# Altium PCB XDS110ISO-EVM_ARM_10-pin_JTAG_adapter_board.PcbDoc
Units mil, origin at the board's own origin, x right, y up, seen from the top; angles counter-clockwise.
Board outline 1100 x 500 mil, 2 copper layers (Top Signal, Bottom Signal), stack 58.8 mil thick; 2 components, 6 nets, 25 pads, 15 vias.
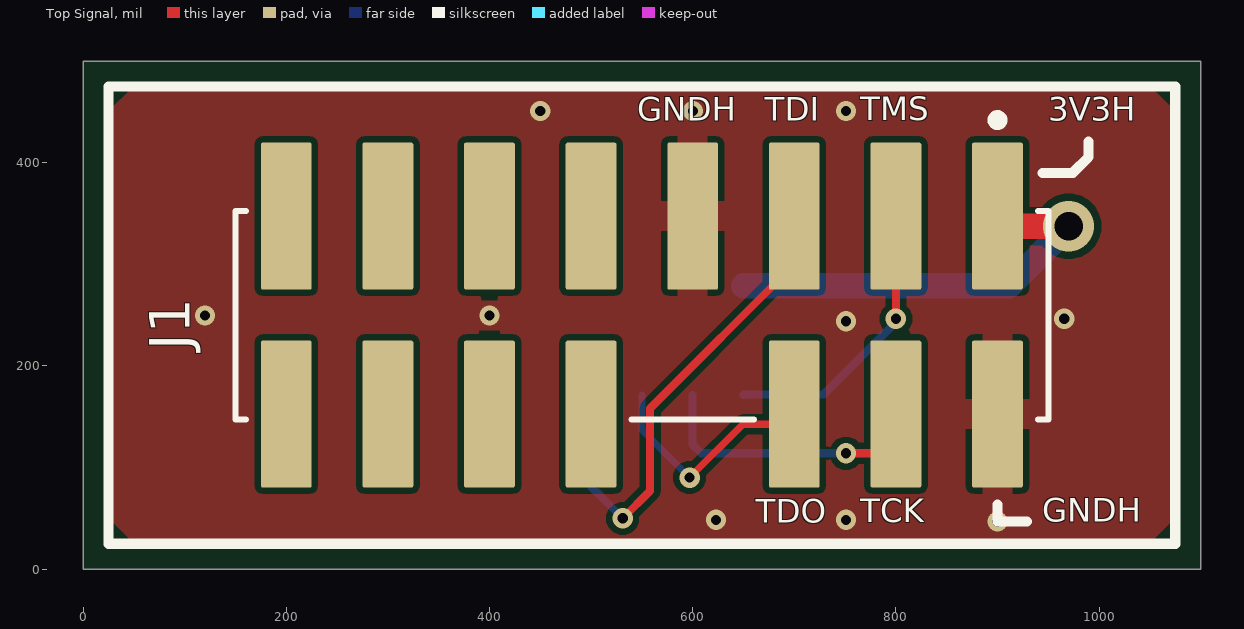
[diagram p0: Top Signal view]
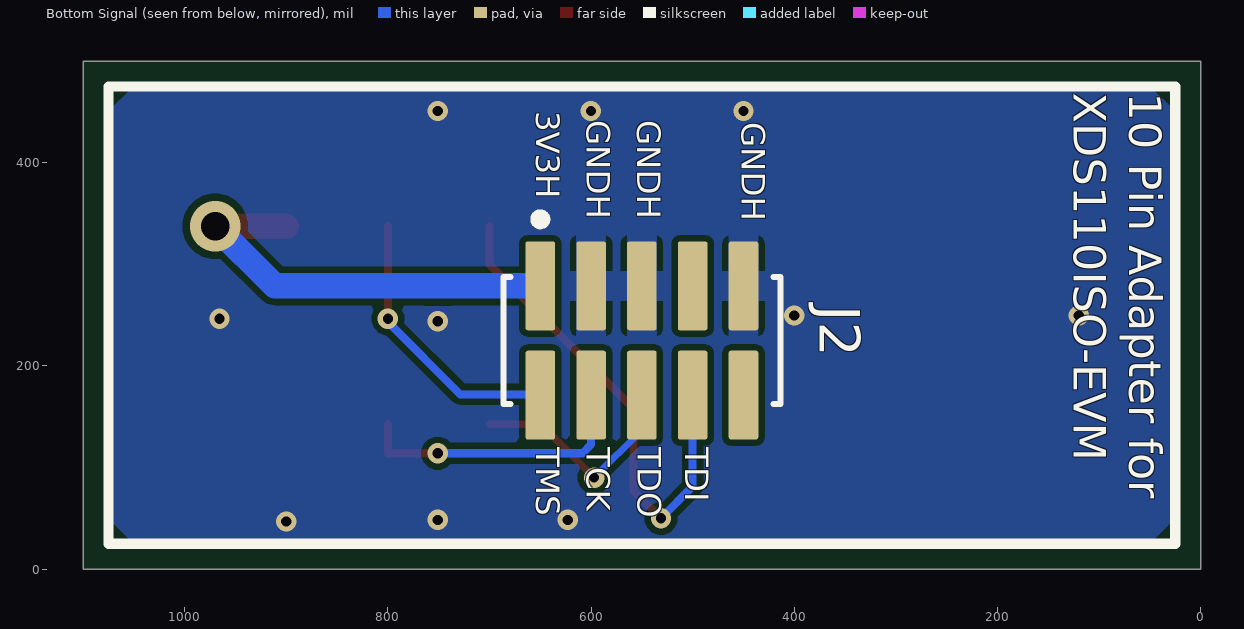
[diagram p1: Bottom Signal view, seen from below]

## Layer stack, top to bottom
Top Solder: solder mask 0.4, Solder Resist, Dk 3.5
Top Signal: signal copper 1.4
Dielectric 1: prepreg 8, FR-4, Dk 4.2
Dielectric 2: core 40, FR-4, Dk 4.2
Dielectric 3: prepreg 8, FR-4, Dk 4.2
Bottom Signal: signal copper 1.4
Bottom Solder: solder mask 0.4, Solder Resist, Dk 3.5

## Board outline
0,0 0,500 1100,500 1100,0

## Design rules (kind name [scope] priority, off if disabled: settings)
AcuteAngle [All] p1: minimum=4.50000000000000E+0001 checktracksonly=TRUE
AssemblyTestPointUsage [All] p1: valid=2
BoardOutlineClearance BoardOutlineClearance_MountingHoles [OnCopper and InComponentClass('Mounting Holes')] p1: gap=40 ignorepadtopadclearanceinfootprint=FALSE
BoardOutlineClearance BoardOutlineClearance_Poly [OnCopper and IsPoly] p2: gap=25 ignorepadtopadclearanceinfootprint=FALSE
BoardOutlineClearance BoardOutlineClearance_USB101 [InComponent('USB101')] p3: gap=0 ignorepadtopadclearanceinfootprint=FALSE
BoardOutlineClearance [OnCopper and Not InComponentClass('Logo') and not InComponentClass('FiducialMark') and not InRegion(1000,500,4000,800) and not InPoly] p4: gap=10 ignorepadtopadclearanceinfootprint=FALSE
Clearance Clearance_NPTH [HoleDiameter = 39] p1: gap=15 ignorepadtopadclearanceinfootprint=FALSE
Clearance Clearance_PTH [HoleDiameter > 10] p2: gap=7 ignorepadtopadclearanceinfootprint=FALSE
Clearance Clearance_FiducialMark [InComponentClass('FiducialMark') vs InComponentClass('FiducialMark')] p3: gap=0 ignorepadtopadclearanceinfootprint=FALSE
Clearance Clearance_Boardedge [All vs IsKeepOut] p4: gap=11.8 ignorepadtopadclearanceinfootprint=FALSE
Clearance [All] p5: gap=6 ignorepadtopadclearanceinfootprint=FALSE
ComponentClearance "ComponentClearance_overlay to overlay" [OnBottomSilkscreen vs OnTopSilkscreen] p1: gap=0 collisioncheckmode=3 verticalgap=0 showdistances=FALSE
ComponentClearance ComponentClearance_MountingHoles_FiducialMarks [InComponentClass('Mounting Holes') vs InComponentClass('FiducialMark')] p2: gap=50 collisioncheckmode=3 verticalgap=10 showdistances=FALSE
ComponentClearance ComponentClearance_Shunt [InComponentClass('Header') vs InComponentClass('Shunt')] p3: gap=0 collisioncheckmode=3 verticalgap=0 showdistances=FALSE
ComponentClearance ComponentClearance_Logo [InComponentClass('Logo')] p4: gap=0 collisioncheckmode=3 verticalgap=0 showdistances=FALSE
ComponentClearance ComponentClearance_Logo_1 [InComponentClass('Logo') vs InComponentClass('Logo')] p5: gap=0 collisioncheckmode=3 verticalgap=0 showdistances=FALSE
ComponentClearance ComponentClearance_ScrewToNut [(HasFootprint('NY PMS 440 0025 PH')) vs (HasFootprint('Keystone_1902C'))] p6: gap=3.94 collisioncheckmode=3 verticalgap=3.94 showdistances=FALSE
ComponentClearance ComponentClearance_MountingHoles [InComponentClass('Mounting Holes')] p7 off: gap=250 collisioncheckmode=3 verticalgap=100000 showdistances=FALSE
ComponentClearance ComponentClearance_SmallPassives [HasFootprint('0201*') or HasFootprint('0402*') or HasFootprint('0508') or HasFootprint('0603*') or HasFootprint('0612') or HasFootprint('0805*') or HasFootprint('0815*') or HasFootprint('0830*') or HasFootprint('1206*') or HasFootprint('1210*') or HasFootprint('1808*') or HasFootprint('1812*') or HasFootprint('1825*') or HasFootprint('2010*') or HasFootprint('2220*') or HasFootprint('2225*') or HasFootprint('2512*') or HasFootprint('2728*') or HasFootprint('3518*') vs HasFootprint('0201*') or HasFootprint('0402*') or HasFootprint('0508') or HasFootprint('0603*') or HasFootprint('0612') or HasFootprint('0805*') or HasFootprint('0815*') or HasFootprint('0830*') or HasFootprint('1206*') or HasFootprint('1210*') or HasFootprint('1808*') or HasFootprint('1812*') or HasFootprint('1825*') or HasFootprint('2010*') or HasFootprint('2220*') or HasFootprint('2225*') or HasFootprint('2512*') or HasFootprint('2728*') or HasFootprint('3518*')] p8 off: gap=10 collisioncheckmode=3 verticalgap=0 showdistances=FALSE
ComponentClearance ComponentClearance_THtoSMT [IsThruComponent vs IsSMTComponent] p9 off: gap=10 collisioncheckmode=3 verticalgap=10 showdistances=FALSE
ComponentClearance ComponentClearance_THtoTH [IsThruComponent vs IsThruComponent] p10 off: gap=20 collisioncheckmode=3 verticalgap=30 showdistances=FALSE
DiffPairsRouting [All] p1: maxlimit=100 minlimit=6 mostfreqgap=6 toplayer_minwidth=5.91 toplayer_maxwidth=15 toplayer_prefwidth=10.63 bottomlayer_minwidth=5.91 bottomlayer_maxwidth=15 bottomlayer_prefwidth=10.63 maxuncoupledlength=1000
FabricationTestPointUsage TestPointUsage [All] p1: valid=2 allowmultiple=FALSE
FabricationTestpoint Testpoint [All] p1: side=3 testpointundercomponent=TRUE minsize=40 maxsize=100 preferedsize=60 minholesize=0 maxholesize=40 preferedholesize=32 testpointgrid=1 allowsidetop=TRUE allowsidebottom=TRUE usegrid=TRUE gridtolerance=0.01
FanoutControl Fanout_LCC [IsLCC] p1: bgadir=Out bgaviamode=Centered fanoutstyle=Auto fanoutdirection=Alternating viagrid=1 // Fanout_LCC (Default Rule)
FanoutControl Fanout_BGA [IsBGA] p2: bgadir=Out bgaviamode=Centered fanoutstyle=Auto fanoutdirection=Alternating viagrid=1 // Fanout_BGA (Default Rule)
FanoutControl Fanout_Default [All] p4: bgadir=Out bgaviamode=Centered fanoutstyle=Auto fanoutdirection=Alternating viagrid=1 // Fanout_Default (Default Rule)
FanoutControl Fanout_Small [(CompPinCount < 5)] p5: bgadir=Out bgaviamode=Centered fanoutstyle=Auto fanoutdirection=OutThenIn viagrid=1 // Fanout_Small (Default Rule)
HoleSize [All] p1: absolutevalues=TRUE maxlimit=251 minlimit=7.87 maxpercent=80.000 minpercent=20.000
HoleToHoleClearance HoleToHoleClearance_USB101 [InComponent('USB101') vs InComponent('USB101')] p1: gap=0 allowstackedmicrovias=TRUE
HoleToHoleClearance [All] p2: gap=12 allowstackedmicrovias=TRUE
MatchedLengths FSIRX [InNetClass('FSIRX')] p1: tolerance=25 checknetsindiffpair=FALSE checkdiffpairvsdiffpair=TRUE checkxsignals=TRUE checkothers=TRUE
MatchedLengths FSITX [InNetClass('FSITX')] p2: tolerance=25 checknetsindiffpair=FALSE checkdiffpairvsdiffpair=TRUE checkxsignals=TRUE checkothers=TRUE
MinimumAnnularRing MinimumAnnularRing_ThermalPadVias [IsVia and InAnyComponent] p1: minimumring=5
MinimumAnnularRing [All] p2: minimumring=5
MinimumSolderMaskSliver MinimumSolderMaskSliver_Logo [InComponentClass('Logo') vs InComponentClass('Logo')] p1: minsoldermaskwidth=0.7
MinimumSolderMaskSliver [All] p2: minsoldermaskwidth=0
PlaneClearance [All] p1: clearance=6
PlaneConnect [All] p1: planeconnectstyle=Relief reliefexpansion=7 reliefentries=4 reliefconductorwidth=8 reliefairgap=6
PolygonConnect PolygonConnect_GNDH [InNet('+3V3H') OR InNet('GNDH')] p1: connectstyle=Relief reliefconductorwidth=30 reliefentries=4 polygonreliefangle="90 Angle" airgapwidth=6
PolygonConnect PolygonConnect_via [isvia] p2: connectstyle=Relief reliefconductorwidth=8 reliefentries=4 polygonreliefangle="90 Angle" airgapwidth=6
PolygonConnect [All] p3: connectstyle=Relief reliefconductorwidth=8 reliefentries=4 polygonreliefangle="90 Angle" airgapwidth=6
RoutingVias RoutingVias_PWR [InNet('+3V3H')] p1: holewidth=28 width=50 viastyle="Through Hole" minholewidth=28 minwidth=50 maxholewidth=28 maxwidth=50
RoutingVias ThermalPadVias [All] p2: holewidth=10 width=20 viastyle="Through Hole" minholewidth=10 minwidth=20 maxholewidth=20 maxwidth=40
RoutingVias [All] p3: holewidth=10 width=20 viastyle="Through Hole" minholewidth=10 minwidth=20 maxholewidth=20 maxwidth=40
SilkToBoardRegionClearance [Not ((IsComment or IsDesignator) And (Hide <> 'False')) and not InRegion(1000,500,4000,800)] p1:
SilkToSilkClearance SilkToSilkClearance_Pb-FreeLogo [(HasFootprint('Pb-Free_Overlay_Medium') OR HasFootprint('Pb-Free_Overlay_Small')) vs (HasFootprint('Pb-Free_Overlay_Medium') OR HasFootprint('Pb-Free_Overlay_Small'))] p1: silktosilkclearance=0
SilkToSilkClearance [All] p2: silktosilkclearance=3
SilkToSolderMaskClearance SilkToComponentPadClearance [(IsPad or IsFill or IsRegion) and InAnycomponent] p1: minsilkscreentomaskgap=2.5 clearancetoexposedcopper=TRUE
SilkToSolderMaskClearance "Silk to Solder Mask Opening" [All] p2: minsilkscreentomaskgap=2.5 clearancetoexposedcopper=TRUE
SolderMaskExpansion [All] p1: expansion=2 istentingtop=FALSE
UnRoutedNet [All] p1: checkbadconnections=TRUE
Width Analog [InNetClass('Analog')] p1: maxlimit=25 minlimit=8 preferedwidth=8
Width [All] p2: maxlimit=100 minlimit=7 preferedwidth=8 minimp=50.000000 maximp=50.000000 favimp=50.000000 checkconnectedcopper=TRUE
12 further rules are at their usual default settings.

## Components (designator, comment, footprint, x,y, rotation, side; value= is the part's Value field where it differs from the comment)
J1 "TSM-108-01-L-DV-008-P-TR" FP-TSM-108-01-L-DV-008-P-TR_HDR15-MFG 550,250 r180 top
J2 "SFMC-105-02-S-D-K-TR" FP-SFMC-105-02-S-D-K-TR_CONN_RCPT10-MFG 550,225 r0 bottom

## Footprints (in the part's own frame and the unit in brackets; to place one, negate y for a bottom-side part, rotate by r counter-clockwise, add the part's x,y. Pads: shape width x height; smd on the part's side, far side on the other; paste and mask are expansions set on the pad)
FP-SFMC-105-02-S-D-K-TR_CONN_RCPT10-MFG [mm]
  rrect14% 0.74x2.22 smd paste+0 mask+0: 1(2.54,-1.365) 2(2.54,1.365) 3(1.27,-1.365) 4(1.27,1.365) 5(0,-1.365) 6(0,1.365) 7(-1.27,-1.365) 8(-1.27,1.365) 9(-2.54,-1.365) 10(-2.54,1.365)
  silkscreen extent -3.47,-3.15 3.47,1.59, body extent -3.37,-2.1 3.37,2.1, height 4.88
FP-TSM-108-01-L-DV-008-P-TR_HDR15-MFG [mm]
  rrect8% 1.27x3.68 smd paste+0 mask+0: 1(-8.89,-2.475) 2(-8.89,2.475) 3(-6.35,-2.475) 4(-6.35,2.475) 5(-3.81,-2.475) 6(-3.81,2.475) 7(-1.27,-2.475) 9(1.27,-2.475) 10(1.27,2.475) 11(3.81,-2.475) 12(3.81,2.475) 13(6.35,-2.475) 14(6.35,2.475) 15(8.89,-2.475) 16(8.89,2.475)
  silkscreen extent -10.16,-5 10.16,2.6, body extent -10.26,-4.42 10.26,4.42, height 0.25

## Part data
J1: library part CMP-0121706-1, "Conn Unshrouded HDR 16 POS 2.54mm Solder ST SMT", Manufacturer=Samtec, Operating Temperature Range="-55°C to +125°C"
J2: library part CMP-0121829-1, "10 Position Receptacle Connector 0.050\" (1.27mm) Surface Mount Gold", Current_A=2.9A, Digikey Part Number=SAM13247CT-ND, Manufacturer=Samtec, Mouser Part Number=200-SFMC10502SDKTR, Operating Temperature Range="-55°C to +125°C", Voltage_V=310V

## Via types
v1: diameter 20, hole 10, Top Signal to Bottom Signal, tented both sides, 14 vias
v2: diameter 50, hole 28, Top Signal to Bottom Signal, tented both sides, 1 vias

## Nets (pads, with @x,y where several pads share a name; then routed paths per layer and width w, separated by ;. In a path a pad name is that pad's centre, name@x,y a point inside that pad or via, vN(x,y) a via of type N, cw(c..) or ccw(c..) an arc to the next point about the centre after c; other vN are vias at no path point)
+3V3H: J1.1 J2.1 | length 414.3
  Top Signal w25: J1.1@900,337.44 v2(970,337.44)
  Bottom Signal w25: J2.1 911.3,278.74 v2(970,337.44)
GNDH: J1.2 J1.7 J2.3 J2.5 J2.9
  other v1: 900,46.82 623.02,48.46 750.98,48.46 750.96,243.98 965.79,246.39 120,249.58 400,249.58 450,450.81 600.18,450.81 750.96,450.81
MCU_TCK: J1.4 J2.4 | length 280.9
  Top Signal w8: v1(750.96,113.99) 800,113.99 J1.4@800,142.56
  Bottom Signal w8: J2.4 600,122.44 608.45,113.99 v1(750.96,113.99)
MCU_TDI: J1.5 J2.8 | length 491.5
  Top Signal w8: v1(531.16,50) 558.15,76.99 558.15,158.15 700,300 J1.5@700,337.44
  Bottom Signal w8: J2.8 500,154.57 500,81.16 v1(531.16,50)
MCU_TDO: J1.6 J2.6 | length 225.5
  Top Signal w7: v1(597,90) 649.56,142.56 J1.6@700,142.56
  Bottom Signal w7: J2.6 550,137 v1(597,90)
MCU_TMS: J1.3 J2.2 | length 274.5
  Top Signal w8: v1(800,246.39) J1.3@800,337.44
  Bottom Signal w8: J2.2 650,171.99 728.77,171.99 800,243.21 v1(800,246.39)
pads on no net: J1.9 J1.10 J1.11 J1.12 J1.13 J1.14 J1.15 J1.16 J2.7 J2.10

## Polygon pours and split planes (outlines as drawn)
GNDH on Bottom Signal "NONET_L-01_P-001" (solid, remove dead copper, pour order 22): 1050,475 50,475 25,450.81 25,50 50,25 1050,25 1075,50 1075,450.81
GNDH on Top Signal "NONET_L-01_P-001" (solid, remove dead copper, pour order 15): 50,475 25,450.81 25,50.49 50,25.49 1050,25.49 1075,50.49 1075.22,450.81 1050,475

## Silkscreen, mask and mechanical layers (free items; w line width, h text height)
Top Overlay:
  lines w10: 900,63.56 900,46.82 928.89,46.82 ; 944.39,390 974.21,390 989.65,405.44 989.65,421 ; 25,25 25,475 1075,475 ; 25,25 1075,25 ; 25,25 1075,25 ; 1075,25 1075,475 ; 1075,25 1075,475
  text "GNDH" at 545.56,433.49 h40
  text "TDI" at 670.72,433.49 h40
  text "TMS" at 765,433.98 h40
  text "3V3H" at 950,433.49 h40
  text "GNDH" at 943.94,38.83 h40
  text "TDO" at 662.24,37.92 h40
  text "TCK" at 765,38.41 h40
Bottom Overlay:
  lines w10: 25,474.51 25,25 1075,25 1075,474.51 ; 25,475 1075,475
  text "10 Pin Adapter for / XDS110ISO-EVM" at 136,468.83 h55 r90
  text "3V3H" at 661.82,450.81 h40 r90
  text "GNDH" at 562.58,441.93 h40 r90
  text "GNDH" at 612.11,441.93 h40 r90
  text "GNDH" at 459.58,440 h40 r90
  text "TDI" at 515,120 h40 r90
  text "TDO" at 562.16,120 h40 r90
  text "TCK" at 612.11,120 h40 r90
  text "TMS" at 661.74,120 h40 r90
M1 Board Outline:
  the board outline again, w10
